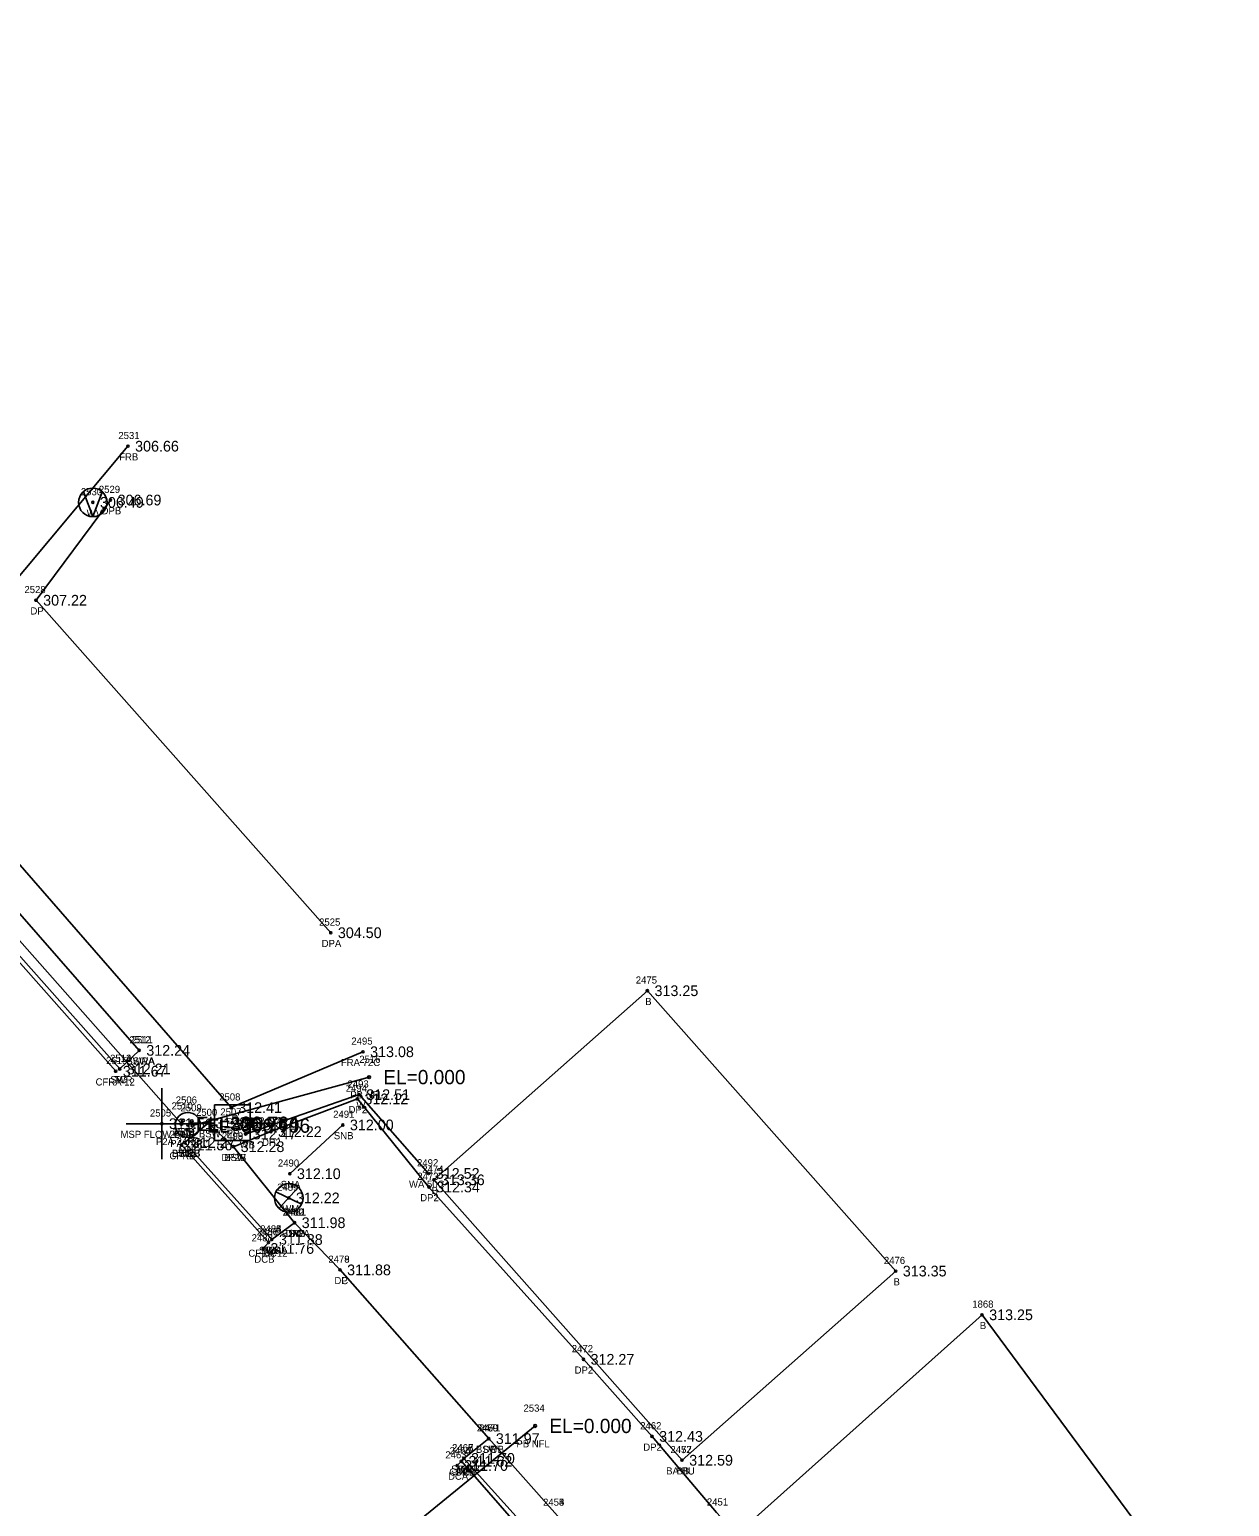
# Model space of a CAD drawing. Extents: x 1970076 to 1971136, y 803126 to 804215.
# Drawn here: x 1970375.4 to 1970543.7, y 803798.1 to 804005.2 of the extents above; entities that cross this region are included whole.
import ezdxf

# ---------------------------------------------------------------- set-up
doc = ezdxf.new("R2010")
doc.units = 0
for name, color, linetype in [('RD_EX_Bldg', 7, 'Continuous'), ('RD_EX_Bldg_txCode', 7, 'Continuous'), ('RD_EX_BldgApp', 7, 'Continuous'), ('RD_EX_BldgApp_txCode', 7, 'Continuous'), ('RD_EX_Conc', 7, 'Continuous'), ('RD_EX_Conc_txCode', 7, 'Continuous'), ('RD_EX_DR_Inlet', 7, 'Continuous'), ('RD_EX_DR_Inlet_txCode', 7, 'Continuous'), ('RD_EX_DR_Pipe', 7, 'Continuous'), ('RD_EX_DR_Pipe_txCode', 7, 'Continuous'), ('RD_EX_Driveway', 7, 'Continuous'), ('RD_EX_Driveway_txCode', 7, 'Continuous'), ('RD_EX_Fence_Other', 7, 'Continuous'), ('RD_EX_Fence_Other_txCode', 7, 'Continuous'), ('RD_EX_Misc', 7, 'Continuous'), ('RD_EX_Misc_txCode', 7, 'Continuous'), ('RD_EX_TX_Bldg_ELEV', 7, 'Continuous'), ('RD_EX_TX_BldgApp_ELEV', 7, 'Continuous'), ('RD_EX_TX_Conc_ELEV', 7, 'Continuous'), ('RD_EX_TX_DR_Inlet_ELEV', 7, 'Continuous'), ('RD_EX_TX_Driveway_ELEV', 7, 'Continuous'), ('RD_EX_TX_Fence_Other_ELEV', 7, 'Continuous'), ('RD_EX_TX_Misc_ELEV', 7, 'Continuous'), ('RD_EX_TX_UT_ELEV', 7, 'Continuous'), ('RD_EX_UT', 7, 'Continuous'), ('RD_EX_UT_txCode', 7, 'Continuous'), ('RD_HC_Survey_ELEV', 7, 'Continuous'), ('RD_SMD_Locator', 7, 'Continuous'), ('RD_TX_Pipe_ElevEX', 7, 'Continuous')]:
    doc.layers.add(name, color=color, linetype=linetype)

msp = doc.modelspace()

# ---------------------------------------------------------------- linework, layer by layer
at = {"layer": 'RD_EX_Bldg'}
for points in [[(1970466.91, 803804.58), (1970432.1, 803843.9), (1970462.05, 803870.41), (1970496.86, 803831.1), (1970466.91, 803804.58)], [(1970543.66, 803778.09), (1970513.97, 803751.4), (1970497.84, 803769.94), (1970475.44, 803794.96), (1970508.97, 803824.97), (1970543.66, 803778.09)]]:
    msp.add_lwpolyline(points, dxfattribs=at)
at = {"layer": 'RD_EX_BldgApp'}
msp.add_line((1970411.91, 803844.75), (1970419.34, 803851.59), dxfattribs=at)
msp.add_lwpolyline([(1970431.38, 803844.79), (1970421.63, 803855.84), (1970405.72, 803850.32)], dxfattribs=at)
at = {"layer": 'RD_EX_Conc'}
for p, q in [((1970390.79, 803862.05), (1970354.1, 803903.96)), ((1970408.92, 803835.11), (1970396.73, 803848.78)), ((1970409.39, 803835.52), (1970397.17, 803849.11)), ((1970449.05, 803797.2), (1970439.8, 803807.61)), ((1970445.25, 803793.84), (1970435.97, 803804.43)), ((1970445.78, 803794.3), (1970436.33, 803804.84))]:
    msp.add_line(p, q, dxfattribs=at)
for points in [[(1970390.79, 803862.05), (1970388.06, 803859.44), (1970351.13, 803901.09), (1970354.1, 803903.96)], [(1970387.5, 803859.12), (1970350.67, 803900.7), (1970351.13, 803901.09)], [(1970412.58, 803837.88), (1970404.02, 803848.54), (1970400.47, 803851.86), (1970397.17, 803849.11)], [(1970435.37, 803803.84), (1970435.97, 803804.43), (1970436.33, 803804.84), (1970439.8, 803807.61), (1970418.95, 803831.27), (1970412.58, 803837.88), (1970409.39, 803835.52), (1970408.92, 803835.11), (1970408.19, 803834.27)]]:
    msp.add_lwpolyline(points, dxfattribs=at)
at = {"layer": 'RD_EX_DR_Inlet'}
for centre, radius in [((1970397.61, 803851.59), 1.75), ((1970396.95, 803852.22), 0.175), ((1970397.52, 803850.92), 0.175), ((1970398.17, 803852.15), 0.175)]:
    msp.add_circle(centre, radius, dxfattribs=at)
at = {"layer": 'RD_EX_DR_Pipe'}
for p, q in [((1970396.71, 803851.76), (1970077.86, 804212.26)), ((1970398.26, 803851.5), (1970423.02, 803858.3)), ((1970391.54, 803764.76), (1970446.31, 803809.39))]:
    msp.add_line(p, q, dxfattribs=at)
at = {"layer": 'RD_EX_Driveway'}
for points in [[(1970417.65, 803878.54), (1970376.33, 803925.16), (1970386.77, 803939.21)], [(1970497.05, 803769.77), (1970471.73, 803797.23), (1970462.7, 803807.92), (1970453.08, 803818.73), (1970431.42, 803842.89), (1970421.38, 803855.24), (1970409.25, 803850.65), (1970404.02, 803848.54)], [(1970484.2, 803757.17), (1970475.49, 803767.3), (1970449.05, 803797.2), (1970439.8, 803807.61), (1970418.95, 803831.27), (1970412.58, 803837.88)]]:
    msp.add_lwpolyline(points, dxfattribs=at)
at = {"layer": 'RD_EX_Fence_Other'}
msp.add_lwpolyline([(1970422.17, 803861.85), (1970403.68, 803854.02), (1970356.7, 803907.94), (1970389.22, 803946.76)], dxfattribs=at)
at = {"layer": 'RD_EX_Misc'}
for p, q in [((1970393.97, 803846.77), (1970393.97, 803856.77)), ((1970388.97, 803851.77), (1970398.97, 803851.77))]:
    msp.add_line(p, q, dxfattribs=at)
at = {"layer": 'RD_EX_UT'}
for p, q in [((1970384.29, 803936.88), (1970382.99, 803940.37)), ((1970384.29, 803936.88), (1970385.61, 803940.33)), ((1970406.33, 803854.42), (1970401.33, 803854.42)), ((1970401.33, 803854.42), (1970401.33, 803849.42)), ((1970406.33, 803849.42), (1970406.33, 803854.42)), ((1970397.9, 803851.86), (1970401.37, 803851.86)), ((1970406.26, 803851.86), (1970409.9, 803851.86)), ((1970401.33, 803849.42), (1970406.33, 803849.42)), ((1970410.42, 803839.9), (1970413.08, 803842.8)), ((1970409.93, 803842.2), (1970413.57, 803840.49))]:
    msp.add_line(p, q, dxfattribs=at)
for centre in [(1970384.29, 803938.88), (1970411.77, 803841.36)]:
    msp.add_circle(centre, 2, dxfattribs=at)
at = {"layer": 'RD_SMD_Locator'}
for centre, radius in [((1970389.22, 803946.76), 0.15), ((1970384.29, 803938.88), 0.15), ((1970386.77, 803939.21), 0.15), ((1970376.33, 803925.16), 0.15), ((1970417.65, 803878.54), 0.15), ((1970462.05, 803870.41), 0.15), ((1970390.79, 803862.05), 0.15), ((1970390.79, 803862.05), 0.15), ((1970422.17, 803861.85), 0.15), ((1970387.5, 803859.12), 0.15), ((1970388.06, 803859.44), 0.15), ((1970388.06, 803859.44), 0.15), ((1970423.02, 803858.3), 0.2), ((1970421.38, 803855.24), 0.15), ((1970421.63, 803855.84), 0.15), ((1970403.68, 803854.02), 0.15), ((1970393.97, 803851.77), 0.15), ((1970396.71, 803851.76), 0.2), ((1970397.61, 803851.59), 0.15), ((1970398.26, 803851.5), 0.2), ((1970400.47, 803851.86), 0.15), ((1970403.84, 803851.92), 0.15), ((1970409.25, 803850.65), 0.15), ((1970419.34, 803851.59), 0.15), ((1970396.73, 803848.78), 0.15), ((1970397.17, 803849.11), 0.15), ((1970397.17, 803849.11), 0.15), ((1970397.17, 803849.11), 0.15), ((1970404.02, 803848.54), 0.15), ((1970404.02, 803848.54), 0.15), ((1970405.72, 803850.32), 0.15), ((1970411.91, 803844.75), 0.15), ((1970431.38, 803844.79), 0.15), ((1970431.42, 803842.89), 0.15), ((1970432.1, 803843.9), 0.15), ((1970411.77, 803841.36), 0.15), ((1970412.58, 803837.88), 0.15), ((1970412.58, 803837.88), 0.15), ((1970412.58, 803837.88), 0.15), ((1970408.19, 803834.27), 0.15), ((1970408.92, 803835.11), 0.15), ((1970408.92, 803835.11), 0.15), ((1970409.39, 803835.52), 0.15), ((1970409.39, 803835.52), 0.15), ((1970409.39, 803835.52), 0.15), ((1970418.95, 803831.27), 0.15), ((1970418.95, 803831.27), 0.15), ((1970496.86, 803831.1), 0.15), ((1970508.97, 803824.97), 0.15), ((1970453.08, 803818.73), 0.15), ((1970446.31, 803809.39), 0.2), ((1970439.8, 803807.61), 0.15), ((1970439.8, 803807.61), 0.15), ((1970439.8, 803807.61), 0.15), ((1970462.7, 803807.92), 0.15), ((1970435.37, 803803.84), 0.15), ((1970435.97, 803804.43), 0.15), ((1970435.97, 803804.43), 0.15), ((1970436.33, 803804.84), 0.15), ((1970436.33, 803804.84), 0.15), ((1970436.33, 803804.84), 0.15), ((1970466.91, 803804.58), 0.15), ((1970466.91, 803804.58), 0.15)]:
    msp.add_circle(centre, radius, dxfattribs=at)

# ---------------------------------------------------------------- texts
at = {"layer": 'RD_EX_Bldg_txCode'}
for s, p in [('2475', (1970460.42, 803871.41)), ('B', (1970461.74, 803868.41)), ('2474', (1970430.47, 803844.9)), ('B', (1970431.8, 803841.9)), ('2476', (1970495.21, 803832.1)), ('B', (1970496.56, 803829.1)), ('1868', (1970507.6, 803825.97)), ('B', (1970508.66, 803822.97)), ('2452', (1970465.28, 803805.58)), ('2477', (1970465.28, 803805.58)), ('BA BU', (1970464.68, 803802.58)), ('BB', (1970466.13, 803802.58))]:
    msp.add_text(s, height=1, dxfattribs=at).set_placement(p)
at = {"layer": 'RD_EX_BldgApp_txCode'}
for s, p in [('2491', (1970417.99, 803852.59)), ('SNB', (1970418.09, 803849.59)), ('2490', (1970410.24, 803845.75)), ('SNA', (1970410.64, 803842.75))]:
    msp.add_text(s, height=1, dxfattribs=at).set_placement(p)
at = {"layer": 'RD_EX_Conc_txCode'}
for s, p in [('2512', (1970389.44, 803863.05)), ('2511', (1970389.73, 803863.05)), ('2515', (1970386.16, 803860.12)), ('2513', (1970386.71, 803860.44)), ('2514', (1970386.71, 803860.44)), ('SWRA', (1970388.99, 803860.05)), ('BSWA', (1970388.99, 803860.05)), ('CFRA 12', (1970384.68, 803857.12)), ('SWR', (1970386.74, 803857.44)), ('TC', (1970387.26, 803857.44)), ('2500', (1970398.76, 803852.86)), ('2504', (1970395.06, 803849.78)), ('2502', (1970395.5, 803850.11)), ('2503', (1970395.5, 803850.11)), ('2501', (1970395.79, 803850.11)), ('BSW', (1970399.16, 803849.86)), ('2499', (1970402.39, 803849.54)), ('CFRB', (1970395.03, 803846.78)), ('SWRB', (1970395.38, 803847.11)), ('BSWB', (1970395.38, 803847.11)), ('TC', (1970396.38, 803847.11)), ('BSW', (1970402.7, 803846.54)), ('2480', (1970410.91, 803838.88)), ('2482', (1970410.95, 803838.88)), ('2488', (1970406.56, 803835.27)), ('2486', (1970407.27, 803836.11)), ('2487', (1970407.29, 803836.11)), ('2483', (1970407.76, 803836.52)), ('2484', (1970407.76, 803836.52)), ('2485', (1970407.76, 803836.52)), ('BSWA', (1970410.78, 803835.88)), ('DC', (1970411.8, 803835.88)), ('CFRA 12', (1970406.1, 803833.11)), ('SWRA', (1970407.59, 803833.52)), ('TCA', (1970408.11, 803833.52)), ('DC', (1970408.14, 803833.11)), ('DC', (1970408.61, 803833.52)), ('DCB', (1970406.94, 803832.27)), ('2478', (1970417.32, 803832.27)), ('DC', (1970418.17, 803829.27)), ('2469', (1970438.15, 803808.61)), ('2471', (1970438.45, 803808.61)), ('2463', (1970433.72, 803804.84)), ('2464', (1970434.32, 803805.43)), ('2465', (1970434.32, 803805.43)), ('2466', (1970434.65, 803805.84)), ('2467', (1970434.67, 803805.84)), ('2468', (1970434.67, 803805.84)), ('BSWB', (1970438.01, 803805.61)), ('DC', (1970439.02, 803805.61)), ('CFRB', (1970434.27, 803802.43)), ('SWRB', (1970434.54, 803802.84)), ('TCB', (1970435.06, 803802.84)), ('DC', (1970435.19, 803802.43)), ('DC', (1970435.55, 803802.84)), ('DCA', (1970434.1, 803801.84)), ('2454', (1970447.42, 803798.2)), ('2455', (1970447.42, 803798.2))]:
    msp.add_text(s, height=1, dxfattribs=at).set_placement(p)
at = {"layer": 'RD_EX_DR_Inlet_txCode'}
for s, p in [('2506', (1970395.92, 803854.59)), ('MHD', (1970396.32, 803847.59))]:
    msp.add_text(s, height=1, dxfattribs=at).set_placement(p)
at = {"layer": 'RD_EX_DR_Pipe_txCode'}
for s, p in [('2516', (1970421.65, 803860.3)), ('PB NFL', (1970420.4, 803855.3)), ('2510', (1970395.33, 803853.76)), ('2509', (1970396.59, 803853.5)), ('P2A 24RC', (1970393.14, 803848.76)), ('PA 24RC', (1970395.14, 803848.5)), ('2534', (1970444.68, 803811.39)), ('PB NFL', (1970443.68, 803806.39))]:
    msp.add_text(s, height=1, dxfattribs=at).set_placement(p)
at = {"layer": 'RD_EX_Driveway_txCode'}
for s, p in [('2529', (1970385.14, 803940.21)), ('DPB', (1970385.52, 803937.21)), ('2528', (1970374.7, 803926.16)), ('DP', (1970375.55, 803923.16)), ('2525', (1970416.02, 803879.54)), ('DPA', (1970416.38, 803876.54)), ('2494', (1970419.75, 803856.24)), ('DP2', (1970420.15, 803853.24)), ('2497', (1970407.62, 803851.65)), ('2498', (1970402.39, 803849.54)), ('DP2', (1970408.02, 803848.65)), ('DP2B', (1970402.32, 803846.54)), ('2473', (1970429.79, 803843.89)), ('DP2', (1970430.19, 803840.89)), ('2481', (1970411.23, 803838.88)), ('DPB', (1970411.33, 803835.88)), ('2479', (1970417.32, 803832.27)), ('DP', (1970418.17, 803829.27)), ('2472', (1970451.45, 803819.73)), ('DP2', (1970451.85, 803816.73)), ('2470', (1970438.13, 803808.61)), ('2462', (1970461.04, 803808.92)), ('DP', (1970439.02, 803805.61)), ('DP2', (1970461.47, 803805.92)), ('2453', (1970447.42, 803798.2)), ('2451', (1970470.39, 803798.23))]:
    msp.add_text(s, height=1, dxfattribs=at).set_placement(p)
at = {"layer": 'RD_EX_Fence_Other_txCode'}
for s, p in [('2531', (1970387.87, 803947.76)), ('FRB', (1970387.99, 803944.76)), ('2495', (1970420.54, 803862.85)), ('FRA 72C', (1970419.07, 803859.85)), ('2508', (1970402.01, 803855.02)), ('FR', (1970402.92, 803852.02))]:
    msp.add_text(s, height=1, dxfattribs=at).set_placement(p)
at = {"layer": 'RD_EX_Misc_txCode'}
for s, p in [('2493', (1970420, 803856.84)), ('W', (1970421.26, 803853.84)), ('2505', (1970392.3, 803852.77)), ('MSP FLOW LINE', (1970388.17, 803849.77)), ('2496', (1970404.07, 803851.32)), ('WB', (1970404.88, 803848.32)), ('2492', (1970429.75, 803845.79)), ('WA 50C', (1970428.62, 803842.79))]:
    msp.add_text(s, height=1, dxfattribs=at).set_placement(p)
at = {"layer": 'RD_EX_TX_Bldg_ELEV'}
for s, p in [('313.25', (1970463.05, 803869.66)), ('313.36', (1970433.1, 803843.15)), ('313.35', (1970497.86, 803830.35)), ('313.25', (1970509.97, 803824.22)), ('312.59', (1970467.91, 803803.83)), ('312.59', (1970467.91, 803803.83))]:
    msp.add_text(s, height=1.5, dxfattribs=at).set_placement(p)
at = {"layer": 'RD_EX_TX_BldgApp_ELEV'}
for s, p in [('312.00', (1970420.34, 803850.84)), ('312.10', (1970412.91, 803844))]:
    msp.add_text(s, height=1.5, dxfattribs=at).set_placement(p)
at = {"layer": 'RD_EX_TX_Conc_ELEV'}
for s, p in [('312.24', (1970391.79, 803861.3)), ('312.24', (1970391.79, 803861.3)), ('311.67', (1970388.5, 803858.37)), ('312.21', (1970389.06, 803858.69)), ('312.21', (1970389.06, 803858.69)), ('312.35', (1970401.47, 803851.11)), ('311.56', (1970397.73, 803848.03)), ('312.27', (1970398.17, 803848.36)), ('312.27', (1970398.17, 803848.36)), ('312.27', (1970398.17, 803848.36)), ('312.28', (1970405.02, 803847.79)), ('311.98', (1970413.58, 803837.13)), ('311.98', (1970413.58, 803837.13)), ('311.88', (1970410.39, 803834.77)), ('311.88', (1970410.39, 803834.77)), ('311.88', (1970410.39, 803834.77)), ('311.76', (1970409.19, 803833.52)), ('311.73', (1970409.92, 803834.36)), ('311.73', (1970409.92, 803834.36)), ('311.88', (1970419.95, 803830.52)), ('311.97', (1970440.8, 803806.86)), ('311.97', (1970440.8, 803806.86)), ('311.62', (1970436.97, 803803.68)), ('311.62', (1970436.97, 803803.68)), ('311.70', (1970437.33, 803804.09)), ('311.70', (1970437.33, 803804.09)), ('311.70', (1970437.33, 803804.09)), ('311.70', (1970436.37, 803803.09))]:
    msp.add_text(s, height=1.5, dxfattribs=at).set_placement(p)
at = {"layer": 'RD_EX_TX_DR_Inlet_ELEV'}
msp.add_text('EL=312.316', height=1.5, dxfattribs=at).set_placement((1970400.61, 803850.84))
at = {"layer": 'RD_EX_TX_Driveway_ELEV'}
for s, p in [('306.69', (1970387.77, 803938.46)), ('307.22', (1970377.33, 803924.41)), ('304.50', (1970418.65, 803877.79)), ('312.12', (1970422.38, 803854.49)), ('312.22', (1970410.25, 803849.9)), ('312.28', (1970405.02, 803847.79)), ('312.34', (1970432.42, 803842.14)), ('311.98', (1970413.58, 803837.13)), ('311.88', (1970419.95, 803830.52)), ('312.27', (1970454.08, 803817.98)), ('311.97', (1970440.8, 803806.86)), ('312.43', (1970463.7, 803807.17))]:
    msp.add_text(s, height=1.5, dxfattribs=at).set_placement(p)
at = {"layer": 'RD_EX_TX_Fence_Other_ELEV'}
for s, p in [('306.66', (1970390.22, 803946.01)), ('313.08', (1970423.17, 803861.1)), ('312.41', (1970404.68, 803853.27))]:
    msp.add_text(s, height=1.5, dxfattribs=at).set_placement(p)
at = {"layer": 'RD_EX_TX_Misc_ELEV'}
for s, p in [('312.51', (1970422.63, 803855.09)), ('311.51', (1970394.97, 803851.02)), ('312.47', (1970406.72, 803849.57)), ('312.52', (1970432.38, 803844.04))]:
    msp.add_text(s, height=1.5, dxfattribs=at).set_placement(p)
at = {"layer": 'RD_EX_TX_UT_ELEV'}
for s, p in [('306.49', (1970385.29, 803938.13)), ('312.22', (1970412.77, 803840.61))]:
    msp.add_text(s, height=1.5, dxfattribs=at).set_placement(p)
at = {"layer": 'RD_EX_UT_txCode'}
for s, p in [('2530', (1970382.62, 803939.88)), ('WV', (1970383.43, 803936.88)), ('2507', (1970402.17, 803852.92)), ('PP', (1970403.06, 803849.92)), ('2489', (1970410.14, 803842.36)), ('WM', (1970410.86, 803839.36))]:
    msp.add_text(s, height=1, dxfattribs=at).set_placement(p)
at = {"layer": 'RD_HC_Survey_ELEV'}
msp.add_text('313.03', height=1.5, dxfattribs=at).set_placement((1970404.84, 803851.17))
at = {"layer": 'RD_TX_Pipe_ElevEX'}
for s, p in [('EL=0.000', (1970425.02, 803857.3)), ('EL=306.764', (1970398.71, 803850.76)), ('EL=306.796', (1970400.26, 803850.5)), ('EL=0.000', (1970448.31, 803808.39))]:
    msp.add_text(s, height=2, dxfattribs=at).set_placement(p)

doc.saveas('drawing.dxf')
